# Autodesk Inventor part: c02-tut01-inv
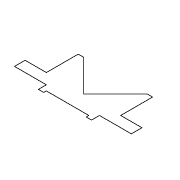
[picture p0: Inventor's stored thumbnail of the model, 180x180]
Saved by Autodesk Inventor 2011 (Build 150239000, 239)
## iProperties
Created: 2010-01
Part Number: c02-tut01-inv
Document SubType Name: Modeling
Designer: CADSoft
Density: 1 g/cm^3
Author: CADSoft
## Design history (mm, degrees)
sketch "Sketch1"
  geometry: L1 (0, 0)-(-3, 3); L2 (-3, 3)-(-3.5, 3); L3 (-3.5, 3)-(-3.5, 0); L4 (-3.5, 0)-(-5.5, 0); L5 (-5.5, 0)-(-5.5, -1); L6 (-5.5, -1)-(-2.5, -1); L7 (-2.5, -1)-(-2.5, -1.75); L8 (-2.5, -1.75)-(-2, -1.75); L9 (-2, -1.75)-(-2, -1.5); L10 (-2, -1.5)-(2, -1.5); L11 (2, -1.5)-(2, -1.75); L12 (2, -1.75)-(2.5, -1.75); L13 (2.5, -1.75)-(2.5, -1); L14 (2.5, -1)-(5.5, -1); L15 (5.5, -1)-(5.5, 0); L16 (5.5, 0)-(3.5, 0); L17 (3.5, 0)-(3.5, 3); L18 (3.5, 3)-(3, 3); L19 (3, 3)-(0, 0)
  constraints: 38 end point, 17 perpendicular, 1 horizontal
